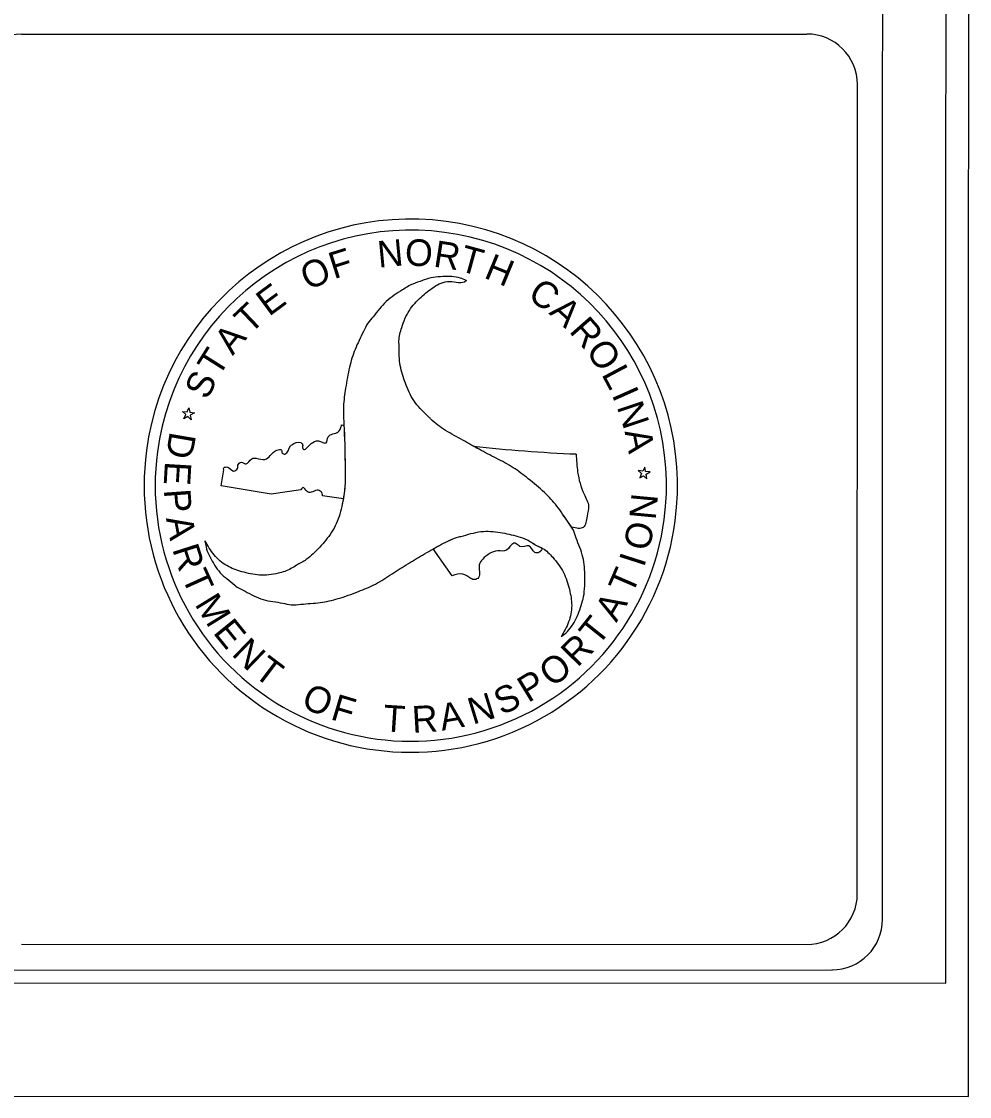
# Model space of a CAD drawing. Extents: x 2105791 to 2114488, y 667759 to 673441.
# Drawn here: x 2113520 to 2114488, y 667759 to 668857 of the extents above; entities that cross this region are included whole.
import ezdxf

# ---------------------------------------------------------------- set-up
doc = ezdxf.new("R2010")
doc.units = 0
for name, color, linetype in [('Sheet Plot Border Inside CELL', 7, 'Continuous'), ('Sheet Plot Border Outside CELL', 7, 'Continuous'), ('Sheet Title CELL', 7, 'Continuous')]:
    doc.layers.add(name, color=color, linetype=linetype)

msp = doc.modelspace()

# ---------------------------------------------------------------- linework, layer by layer
at = {"layer": 'Sheet Plot Border Inside CELL'}
msp.add_lwpolyline([(2105858.2, 667876.6), (2114463.6, 667875.1), (2114464.5, 673323.4), (2105859.1, 673324.8)], close=True, dxfattribs=at)
at = {"layer": 'Sheet Plot Border Outside CELL'}
msp.add_lwpolyline([(2114487.7, 673439.3), (2105792, 673440.8), (2105791, 667760.7), (2114486.8, 667759.2)], close=True, dxfattribs=at)
at = {"layer": 'Sheet Title CELL'}
for p, q in [((2113520.1, 668843.8), (2114321.7, 668843.7)), ((2113974.5, 668592.7), (2113974, 668592.2)), ((2113974.5, 668592.7), (2113974, 668592.2)), ((2113689.1, 668458.1), (2113691, 668462.3)), ((2113691, 668462.3), (2113692, 668457.7)), ((2113687.8, 668455.4), (2113684.4, 668458.7)), ((2113684.4, 668458.7), (2113689.1, 668458.1)), ((2113685.9, 668451.1), (2113687.8, 668455.4)), ((2113689.8, 668453.5), (2113685.9, 668451.1)), ((2113693.3, 668450.2), (2113689.8, 668453.5)), ((2113692, 668457.7), (2113696.7, 668457.1)), ((2113696.7, 668457.1), (2113692.4, 668454.8)), ((2113692.4, 668454.8), (2113693.3, 668450.2)), ((2113981.3, 668423.2), (2113981.3, 668423.2)), ((2113723.9, 668382.7), (2113726.7, 668398.9)), ((2114154.2, 668397.7), (2114149.5, 668398.3)), ((2114149.5, 668398.3), (2114153, 668395.1)), ((2114156.2, 668401.8), (2114154.2, 668397.7)), ((2114157.2, 668397.3), (2114156.2, 668401.8)), ((2114161.8, 668396.9), (2114157.2, 668397.3)), ((2114157.6, 668394.5), (2114161.8, 668396.9)), ((2114153, 668395.1), (2114151.1, 668390.8)), ((2114151.1, 668390.8), (2114155, 668393)), ((2114155, 668393), (2114158.4, 668389.8)), ((2114158.4, 668389.8), (2114157.6, 668394.5)), ((2113774.9, 668374), (2113723.9, 668382.7)), ((2113805.4, 668378.7), (2113774.9, 668374)), ((2113848.8, 668369.3), (2113827.5, 668372.4)), ((2114187.3, 668346.9), (2114187.3, 668346.9)), ((2113959.8, 668290.8), (2113940.4, 668318.3)), ((2113940.4, 668318.3), (2113940.4, 668318.3)), ((2113520, 667914.6), (2114321.6, 667914.4))]:
    msp.add_line(p, q, dxfattribs=at)
for points in [[(2114399, 667940), (2114399.9, 673258.6)], [(2114373.2, 667965.8), (2114373.3, 668792)], [(2106705, 667889.6), (2114347.4, 667888.3)]]:
    msp.add_lwpolyline(points, dxfattribs=at)
for centre, radius, start, end in [((2113520.1, 668792.2), 51.6, 89.9903, 179.9903), ((2114321.7, 668792.3), 51.6, 359.9903, 89.9903), ((2113917.5, 668382.8), 272.2, 352.4114, 172.4114), ((2113917.5, 668382.8), 260.9, 352.4114, 172.4114), ((2114143.1, 669849.3), 1435.2, 258.0899, 258.1895), ((2113917.5, 668382.8), 272.2, 172.4114, 352.4114), ((2114143.1, 669849.3), 1435.2, 263.529, 267.735), ((2113917.5, 668382.8), 260.9, 172.4114, 352.4114), ((2114321.6, 667966.1), 51.6, 269.9903, 359.9903), ((2114347.4, 667940.2), 51.6, 269.9903, 359.9903)]:
    msp.add_arc(centre, radius, start, end, dxfattribs=at)
for points in [[(2113974, 668592.2), (2113968.1, 668594.7), (2113950.1, 668596.3), (2113931.1, 668592.9), (2113929.4, 668592.2), (2113919.6, 668588.7), (2113909, 668582.7), (2113892.5, 668570.9), (2113879, 668555.3), (2113873.6, 668548.6), (2113869.1, 668540.1), (2113860.6, 668521.9), (2113855, 668503.9), (2113851, 668482.5), (2113848.8, 668463.6), (2113849.3, 668443.9), (2113850.1, 668424.1), (2113850.4, 668404.8), (2113850.4, 668385), (2113847.9, 668365.7), (2113847.6, 668364.1), (2113841.4, 668344), (2113830.7, 668327.1), (2113818, 668313.4), (2113810.8, 668307.3), (2113800.8, 668301.5), (2113795.1, 668298.1), (2113782.1, 668293.4), (2113763, 668291.6), (2113745.1, 668295), (2113729.6, 668301.2), (2113716.7, 668312.2), (2113707.4, 668326.6)], [(2114070.9, 668228.6), (2114075.7, 668232.4), (2114086.2, 668247.1), (2114092.8, 668265.3), (2114093.3, 668267.1), (2114094.8, 668277.4), (2114095.1, 668289.7), (2114093.2, 668309.9), (2114086.3, 668329.2), (2114083.4, 668337.3), (2114078.1, 668345.6), (2114066.6, 668362), (2114053.9, 668375.8), (2114037.4, 668389.9), (2114022, 668401.2), (2114004.7, 668410.8), (2113987.2, 668420), (2113970.5, 668429.3), (2113953, 668439.2), (2113937.7, 668451), (2113936.5, 668452.2), (2113922, 668467.6), (2113912.8, 668485.4), (2113907.2, 668503.1), (2113905.8, 668512.4), (2113905.7, 668524), (2113905.4, 668530.7), (2113908.2, 668544.2), (2113916, 668561.8), (2113927.9, 668575.4), (2113941, 668585.6), (2113957, 668591.3), (2113974, 668592.2), (2113974.5, 668592.7)], [(2113726.7, 668398.9), (2113726.3, 668400.5), (2113729.3, 668401.9), (2113736.5, 668397.8), (2113740.7, 668400.5), (2113741, 668403.8), (2113744.5, 668406.7), (2113749.5, 668405), (2113755.1, 668410.3), (2113759.5, 668410.8), (2113768.6, 668409.6), (2113780.9, 668419), (2113785.5, 668419.1), (2113786.3, 668416), (2113789, 668415.1), (2113794.8, 668423.4), (2113796.2, 668424.6), (2113805.1, 668426.8), (2113807.1, 668424.9), (2113807.2, 668420.8), (2113808.3, 668419.9), (2113811.4, 668421.5), (2113815.8, 668425.8), (2113823.2, 668428.5), (2113831, 668426.4), (2113833.2, 668432.7), (2113843.4, 668437.7), (2113845.8, 668441.2), (2113846.8, 668445)], [(2113849.3, 668444.4), (2113849.3, 668443.9), (2113850.1, 668424.1), (2113850.4, 668404.8), (2113850.4, 668385), (2113848.7, 668369.3)], [(2114081.7, 668340.5), (2114078.1, 668345.6), (2114066.6, 668362), (2114053.9, 668375.8), (2114037.4, 668389.9), (2114022, 668401.2), (2114004.7, 668410.8), (2113987.2, 668420), (2113981.3, 668423.2)], [(2114086.3, 668415.1), (2114087.8, 668396.6), (2114094.4, 668374.2), (2114098.9, 668361.8), (2114097.4, 668351.8), (2114093.5, 668340.2), (2114081.8, 668340.5)], [(2113827.5, 668372.4), (2113825.9, 668376.6), (2113821.9, 668378.3), (2113815.9, 668376.1), (2113811.7, 668376.9), (2113807.5, 668380.9), (2113805.4, 668378.7)], [(2113707.4, 668326.6), (2113708.5, 668320.3), (2113716, 668303.8), (2113728.3, 668289), (2113729.7, 668288), (2113737.8, 668281.1), (2113748.3, 668275), (2113766.8, 668266.5), (2113786.8, 668262.9), (2113795.4, 668261.3), (2113805.4, 668261.8), (2113825, 668263.5), (2113843.3, 668267.5), (2113864, 668274.8), (2113881.3, 668282.3), (2113898.3, 668292.7), (2113915, 668303.4), (2113931.6, 668313.2), (2113948.8, 668323), (2113966.6, 668330.6), (2113968.6, 668331.1), (2113989.1, 668335.9), (2114008.8, 668335), (2114026.8, 668331), (2114036.1, 668327.7), (2114045.8, 668321.8), (2114052, 668318.8), (2114062.3, 668309.7), (2114073.3, 668294.1), (2114079.3, 668277), (2114081.7, 668260.4), (2114078.6, 668243.8), (2114070.9, 668228.6)], [(2113940.4, 668318.3), (2113948.8, 668323), (2113966.6, 668330.6), (2113968.6, 668331.1), (2113989.1, 668335.9), (2114008.8, 668335), (2114026.8, 668331), (2114036.1, 668327.7), (2114045.8, 668321.8), (2114051.5, 668318.9)], [(2114051.4, 668318.8), (2114048.3, 668314.5), (2114044.2, 668314.7), (2114037.9, 668321.3), (2114028.9, 668320.7), (2114025.2, 668323.6), (2114022.6, 668324), (2114015.2, 668316.9), (2114006.3, 668316.2), (2113990.9, 668307.7), (2113987.3, 668302.1), (2113986.6, 668289), (2113982.8, 668286.9), (2113978.7, 668288.1), (2113970.5, 668292.6), (2113959.8, 668290.8)]]:
    msp.add_spline(points, degree=3, dxfattribs=at)

# ---------------------------------------------------------------- texts
for s, height, rotation, p in [('N', 27.1, 5.3952, (2113884.7, 668605.3)), ('O', 27.2, 357.8971, (2113911.2, 668607.6)), ('R', 27.1, 351.2872, (2113939.8, 668606.6)), ('T', 27.2, 344.6375, (2113965.5, 668602.6)), ('F', 27.2, 17.4822, (2113839, 668593.5)), ('H', 27.1, 337.5528, (2113991.1, 668595.4)), ('O', 27.2, 24.629, (2113812.8, 668581.7)), ('E', 27.1, 36.5684, (2113772.8, 668555)), ('C', 27.1, 325.2105, (2114035.5, 668574.4)), ('A', 27.1, 317.7134, (2114057.7, 668558.8)), ('T', 27.1, 43.684, (2113753.5, 668536.7)), ('R', 27.1, 311.3495, (2114078.3, 668540.1)), ('A', 27.2, 50.7392, (2113735.7, 668515)), ('O', 27.2, 304.2299, (2114095.4, 668520.6)), ('T', 27.2, 57.7915, (2113721.3, 668492.7)), ('L', 27.1, 297.9962, (2114111.7, 668496.7)), ('S', 27.1, 64.1677, (2113709.9, 668469.5)), ('I', 27.2, 294.0069, (2114122.2, 668475.7)), ('N', 27.1, 288.3068, (2114127.5, 668463.5)), ('D', 27.1, 260.2644, (2113671.7, 668438.8)), ('A', 27.1, 280.8748, (2114135.6, 668438.2)), ('E', 27, 266.5523, (2113666.7, 668408)), ('P', 27.1, 274.0847, (2113665.4, 668378.6)), ('N', 27.1, 84.6196, (2114167.4, 668347.3)), ('A', 27.1, 280.6773, (2113667.5, 668349.6)), ('O', 27, 77.3715, (2114160.5, 668315.2)), ('R', 27.1, 287.7459, (2113673.8, 668318.1)), ('I', 27.2, 72.2359, (2114155.4, 668298.6)), ('T', 27.1, 294.3965, (2113683.2, 668289.7)), ('T', 27.1, 66.586, (2114143.3, 668270.4)), ('M', 27.1, 301.6315, (2113696.4, 668261.8)), ('A', 27.2, 59.5016, (2114127.3, 668242.5)), ('E', 27.1, 309.0983, (2113714.9, 668232.7)), ('T', 27.1, 51.4145, (2114108.5, 668218.1)), ('N', 27.2, 316.0698, (2113733.7, 668210.2)), ('R', 27.2, 45.3148, (2114087.6, 668196.5)), ('T', 27.1, 322.9118, (2113755.9, 668189.2)), ('O', 27.2, 38.1257, (2114062, 668176.1)), ('P', 27.1, 31.4337, (2114037.3, 668160.7)), ('O', 27.1, 336.2155, (2113804.4, 668157.4)), ('S', 27, 24.2418, (2114010, 668148.2)), ('F', 27.1, 343.3807, (2113834.6, 668144.6)), ('N', 27.1, 17.0313, (2113980.8, 668138.7)), ('T', 27.1, 356.29, (2113888.7, 668132.2)), ('R', 27.2, 3.2466, (2113919.4, 668130.5)), ('A', 27.1, 9.9997, (2113949.3, 668132.6))]:
    msp.add_text(s, height=height, rotation=rotation, dxfattribs=at).set_placement(p)

doc.saveas('drawing.dxf')
